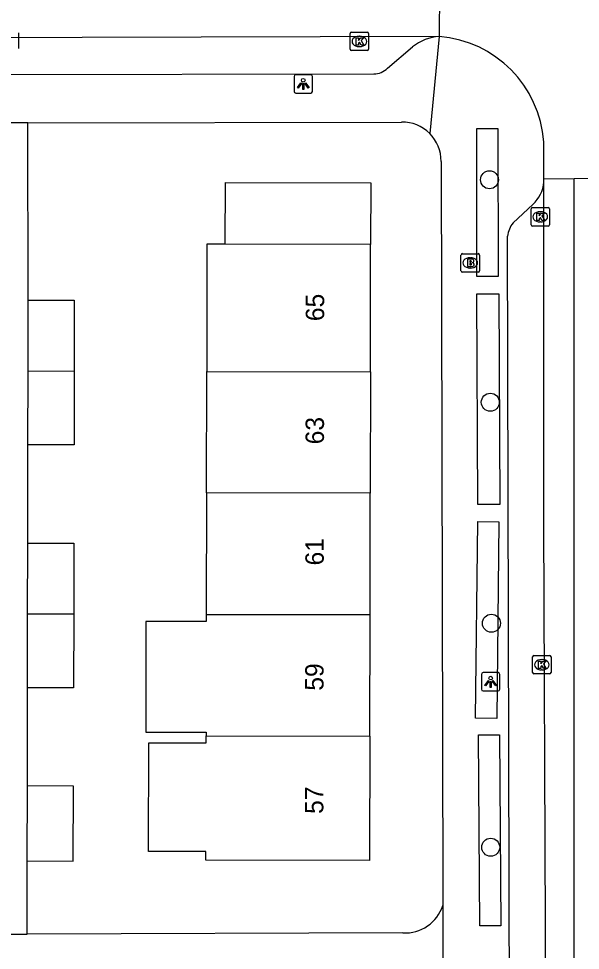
# Model space of a CAD drawing. Extents: x 160732 to 162105, y 387428 to 388479.
# Drawn here: x 161271.9 to 161302.4, y 388097.7 to 388148.3 of the extents above; entities that cross this region are included whole.
import ezdxf

# ---------------------------------------------------------------- set-up
doc = ezdxf.new("R2010")
doc.units = 0
for name, color, linetype in [('IMGEO_Boom', 7, 'Continuous'), ('IMGEO_Brandkraan', 7, 'Continuous'), ('IMGEO_Kolk', 7, 'Continuous'), ('IMGEO_Lichtpunt', 7, 'Continuous'), ('IMGEO_Pand', 7, 'Continuous'), ('IMGEO_Pand_nummerreeks', 7, 'Continuous'), ('IMGEO_Rijbaan_lokaal_gesloten', 7, 'Continuous'), ('IMGEO_Rijbaan_lokaal_open', 7, 'Continuous'), ('IMGEO_Voetpad_open', 7, 'Continuous')]:
    doc.layers.add(name, color=color, linetype=linetype)

msp = doc.modelspace()

# ---------------------------------------------------------------- linework, layer by layer
at = {"layer": 'IMGEO_Boom'}
for centre in [(161297.473, 388139.553), (161297.518, 388127.461), (161297.578, 388115.457), (161297.538, 388103.288)]:
    msp.add_circle(centre, 0.489, dxfattribs=at)
at = {"layer": 'IMGEO_Brandkraan'}
for p, q in [((161295.999, 388135.535), (161296.851, 388135.535)), ((161295.924, 388134.609), (161295.924, 388135.461)), ((161296.412, 388135.315), (161296.437, 388135.315)), ((161296.925, 388135.461), (161296.925, 388134.609)), ((161296.851, 388134.535), (161295.999, 388134.535)), ((161296.435, 388134.755), (161296.41, 388134.755))]:
    msp.add_line(p, q, dxfattribs=at)
for points in [[(161295.999, 388135.535), (161296.851, 388135.535)], [(161295.924, 388134.609), (161295.924, 388135.461)], [(161296.272, 388135.235), (161296.272, 388134.835), (161296.485, 388134.835)], [(161296.503, 388135.235), (161296.272, 388135.235)], [(161296.451, 388135.154), (161296.397, 388135.154), (161296.397, 388135.078)], [(161296.397, 388135.078), (161296.45, 388135.078)], [(161296.459, 388135.002), (161296.397, 388135.002), (161296.397, 388134.921)], [(161296.925, 388135.461), (161296.925, 388134.609)], [(161296.851, 388134.535), (161295.999, 388134.535)], [(161296.397, 388134.921), (161296.459, 388134.921)]]:
    msp.add_lwpolyline(points, dxfattribs=at)
for centre, radius, start, end in [((161296.001, 388135.459), 0.0765, 91.552, 178.448), ((161296.001, 388135.459), 0.0765, 91.552, 178.448), ((161296.849, 388135.459), 0.0765, 1.552, 88.448), ((161296.849, 388135.459), 0.0765, 1.552, 88.448), ((161296.452, 388135.116), 0.0379, 267.8285, 90.9355), ((161296.46, 388134.961), 0.0404, 269.8759, 90.5077), ((161296.507, 388135.09), 0.145, 59.4692, 91.5367), ((161296.532, 388135.137), 0.0922, 285.5137, 58.1501), ((161296.537, 388134.945), 0.105, 301.3115, 78.989), ((161296.001, 388134.611), 0.0765, 181.552, 268.448), ((161296.001, 388134.611), 0.0765, 181.552, 268.448), ((161296.491, 388135.086), 0.251, 268.6676, 293.5347), ((161296.849, 388134.611), 0.0765, 271.552, 358.448), ((161296.849, 388134.611), 0.0765, 271.552, 358.448)]:
    msp.add_arc(centre, radius, start, end, dxfattribs=at)
for centre, major_axis, ratio, start_param, end_param in [((161296.411, 388135.035), (-0.387, 0.002), 0.722429, 4.712389, 7.853982), ((161296.436, 388135.035), (-0.39, 0.002), 0.717154, 1.570796, 4.712389)]:
    msp.add_ellipse(centre, major_axis=major_axis, ratio=ratio, start_param=start_param, end_param=end_param, dxfattribs=at)
at = {"layer": 'IMGEO_Kolk'}
for p, q in [((161271.882, 388147.531), (161271.882, 388146.679)), ((161289.901, 388146.641), (161289.901, 388147.493)), ((161289.976, 388147.567), (161290.828, 388147.567)), ((161290.389, 388147.347), (161290.414, 388147.347)), ((161290.902, 388147.493), (161290.902, 388146.641)), ((161290.412, 388146.787), (161290.387, 388146.787)), ((161290.828, 388146.567), (161289.976, 388146.567)), ((161299.805, 388138.036), (161300.657, 388138.036)), ((161299.73, 388137.11), (161299.73, 388137.962)), ((161300.218, 388137.816), (161300.243, 388137.816)), ((161300.731, 388137.962), (161300.731, 388137.11)), ((161300.657, 388137.036), (161299.805, 388137.036)), ((161300.241, 388137.256), (161300.216, 388137.256)), ((161299.816, 388112.774), (161299.816, 388113.626)), ((161299.891, 388113.7), (161300.743, 388113.7)), ((161300.304, 388113.48), (161300.329, 388113.48)), ((161300.817, 388113.626), (161300.817, 388112.774)), ((161300.327, 388112.92), (161300.302, 388112.92)), ((161300.743, 388112.7), (161299.891, 388112.7))]:
    msp.add_line(p, q, dxfattribs=at)
for points in [[(161271.882, 388147.531), (161271.882, 388146.679)], [(161289.901, 388146.641), (161289.901, 388147.493)], [(161289.976, 388147.567), (161290.828, 388147.567)], [(161290.222, 388147.267), (161290.345, 388147.267), (161290.345, 388147.116), (161290.475, 388147.267), (161290.639, 388147.267), (161290.493, 388147.116), (161290.646, 388146.867), (161290.494, 388146.867), (161290.409, 388147.031), (161290.345, 388146.964), (161290.345, 388146.867), (161290.222, 388146.867), (161290.222, 388147.267)], [(161290.902, 388147.493), (161290.902, 388146.641)], [(161290.828, 388146.567), (161289.976, 388146.567)], [(161299.805, 388138.036), (161300.657, 388138.036)], [(161299.73, 388137.11), (161299.73, 388137.962)], [(161300.051, 388137.736), (161300.174, 388137.736), (161300.174, 388137.585), (161300.304, 388137.736), (161300.468, 388137.736), (161300.322, 388137.585), (161300.475, 388137.336), (161300.323, 388137.336), (161300.238, 388137.5), (161300.174, 388137.433), (161300.174, 388137.336), (161300.051, 388137.336), (161300.051, 388137.736)], [(161300.731, 388137.962), (161300.731, 388137.11)], [(161300.657, 388137.036), (161299.805, 388137.036)], [(161299.816, 388112.774), (161299.816, 388113.626)], [(161299.891, 388113.7), (161300.743, 388113.7)], [(161300.137, 388113.4), (161300.26, 388113.4), (161300.26, 388113.249), (161300.39, 388113.4), (161300.554, 388113.4), (161300.408, 388113.249), (161300.561, 388113), (161300.409, 388113), (161300.324, 388113.164), (161300.26, 388113.097), (161300.26, 388113), (161300.137, 388113), (161300.137, 388113.4)], [(161300.817, 388113.626), (161300.817, 388112.774)], [(161300.743, 388112.7), (161299.891, 388112.7)]]:
    msp.add_lwpolyline(points, dxfattribs=at)
for centre, start, end in [((161289.978, 388147.491), 91.552, 178.448), ((161289.978, 388147.491), 91.552, 178.448), ((161290.826, 388147.491), 1.552, 88.448), ((161290.826, 388147.491), 1.552, 88.448), ((161289.978, 388146.643), 181.552, 268.448), ((161289.978, 388146.643), 181.552, 268.448), ((161290.826, 388146.643), 271.552, 358.448), ((161290.826, 388146.643), 271.552, 358.448), ((161299.807, 388137.96), 91.552, 178.448), ((161299.807, 388137.96), 91.552, 178.448), ((161300.655, 388137.96), 1.552, 88.448), ((161300.655, 388137.96), 1.552, 88.448), ((161299.807, 388137.112), 181.552, 268.448), ((161299.807, 388137.112), 181.552, 268.448), ((161300.655, 388137.112), 271.552, 358.448), ((161300.655, 388137.112), 271.552, 358.448), ((161299.893, 388113.624), 91.552, 178.448), ((161299.893, 388113.624), 91.552, 178.448), ((161300.741, 388113.624), 1.552, 88.448), ((161300.741, 388113.624), 1.552, 88.448), ((161299.893, 388112.776), 181.552, 268.448), ((161299.893, 388112.776), 181.552, 268.448), ((161300.741, 388112.776), 271.552, 358.448), ((161300.741, 388112.776), 271.552, 358.448)]:
    msp.add_arc(centre, 0.0765, start, end, dxfattribs=at)
for centre, major_axis, ratio, start_param, end_param in [((161290.388, 388147.067), (-0.387, 0.002), 0.722429, 4.712389, 7.853982), ((161290.413, 388147.067), (-0.39, 0.002), 0.717154, 1.570796, 4.712389), ((161300.217, 388137.536), (-0.387, 0.002), 0.722429, 4.712389, 7.853982), ((161300.242, 388137.536), (-0.39, 0.002), 0.717154, 1.570796, 4.712389), ((161300.303, 388113.2), (-0.387, 0.002), 0.722429, 4.712389, 7.853982), ((161300.328, 388113.2), (-0.39, 0.002), 0.717154, 1.570796, 4.712389)]:
    msp.add_ellipse(centre, major_axis=major_axis, ratio=ratio, start_param=start_param, end_param=end_param, dxfattribs=at)
at = {"layer": 'IMGEO_Lichtpunt'}
for p, q in [((161286.854, 388145.159), (161286.854, 388144.352)), ((161286.854, 388145.159), (161286.854, 388144.352)), ((161287.756, 388145.254), (161286.948, 388145.254)), ((161287.756, 388145.254), (161286.948, 388145.254)), ((161287.85, 388144.352), (161287.85, 388145.159)), ((161287.85, 388144.352), (161287.85, 388145.159)), ((161286.948, 388144.258), (161287.756, 388144.258)), ((161286.948, 388144.258), (161287.756, 388144.258)), ((161297.94, 388112.774), (161297.132, 388112.774)), ((161297.94, 388112.774), (161297.132, 388112.774)), ((161297.038, 388112.679), (161297.038, 388111.872)), ((161297.038, 388112.679), (161297.038, 388111.872)), ((161298.034, 388111.872), (161298.034, 388112.679)), ((161298.034, 388111.872), (161298.034, 388112.679)), ((161297.132, 388111.778), (161297.94, 388111.778)), ((161297.132, 388111.778), (161297.94, 388111.778))]:
    msp.add_line(p, q, dxfattribs=at)
for points in [[(161287.228, 388144.823), (161287.267, 388144.795), (161287.079, 388144.533), (161287.041, 388144.56), (161287.228, 388144.823)], [(161287.33, 388144.775), (161287.377, 388144.775), (161287.377, 388144.453), (161287.33, 388144.453), (161287.33, 388144.775)], [(161287.44, 388144.795), (161287.478, 388144.822), (161287.665, 388144.56), (161287.626, 388144.532), (161287.44, 388144.795)], [(161297.412, 388112.343), (161297.451, 388112.315), (161297.263, 388112.053), (161297.225, 388112.08), (161297.412, 388112.343)], [(161297.514, 388112.295), (161297.561, 388112.295), (161297.561, 388111.973), (161297.514, 388111.973), (161297.514, 388112.295)], [(161297.624, 388112.315), (161297.662, 388112.342), (161297.849, 388112.08), (161297.81, 388112.052), (161297.624, 388112.315)]]:
    msp.add_lwpolyline(points, dxfattribs=at)
for centre in [(161287.353, 388144.957), (161297.537, 388112.477)]:
    msp.add_circle(centre, 0.0994, dxfattribs=at)
for centre, start, end in [((161286.948, 388145.159), 90, 180), ((161286.948, 388145.159), 90, 180), ((161287.756, 388145.159), 0, 90), ((161287.756, 388145.159), 0, 90), ((161286.948, 388144.352), 180, 270), ((161286.948, 388144.352), 180, 270), ((161287.756, 388144.352), 270, 0), ((161287.756, 388144.352), 270, 360), ((161297.132, 388112.679), 90, 180), ((161297.132, 388112.679), 90, 180), ((161297.94, 388112.679), 0, 90), ((161297.94, 388112.679), 0, 90), ((161297.132, 388111.872), 180, 270), ((161297.132, 388111.872), 180, 270), ((161297.94, 388111.872), 270, 0), ((161297.94, 388111.872), 270, 360)]:
    msp.add_arc(centre, 0.0946, start, end, dxfattribs=at)
at = {"layer": 'IMGEO_Pand'}
for points in [[(161283.115, 388136.046), (161283.121, 388139.396), (161291.019, 388139.383), (161291.013, 388136.036)], [(161283.115, 388136.046), (161282.115, 388136.048), (161282.104, 388129.133)], [(161291.013, 388136.036), (161283.115, 388136.046)], [(161291.002, 388129.123), (161291.013, 388136.036)], [(161272.392, 388129.144), (161272.399, 388133.004)], [(161272.399, 388133.004), (161274.908, 388133), (161274.901, 388129.141)], [(161272.384, 388125.153), (161272.392, 388129.144)], [(161274.901, 388129.141), (161274.893, 388125.148), (161272.384, 388125.153)], [(161274.901, 388129.141), (161272.392, 388129.144)], [(161282.093, 388122.533), (161282.104, 388129.133)], [(161282.104, 388129.133), (161291.002, 388129.123)], [(161291.002, 388129.123), (161290.991, 388122.523)], [(161282.093, 388122.533), (161282.082, 388115.933)], [(161290.991, 388122.523), (161282.093, 388122.533)], [(161290.98, 388115.923), (161290.991, 388122.523)], [(161272.37, 388115.944), (161272.377, 388119.804)], [(161272.377, 388119.804), (161274.886, 388119.8), (161274.879, 388115.941)], [(161272.362, 388111.953), (161272.37, 388115.944)], [(161274.879, 388115.941), (161274.871, 388111.948), (161272.362, 388111.953)], [(161274.879, 388115.941), (161272.37, 388115.944)], [(161282.082, 388115.933), (161282.081, 388115.551), (161278.799, 388115.554), (161278.792, 388109.538), (161282.071, 388109.534), (161282.071, 388109.334)], [(161282.082, 388115.933), (161290.98, 388115.923)], [(161290.969, 388109.324), (161290.98, 388115.923)], [(161290.969, 388109.324), (161290.958, 388102.573), (161282.06, 388102.587), (161282.061, 388103.051), (161278.946, 388103.056), (161278.956, 388108.956), (161282.07, 388108.951), (161282.071, 388109.334)], [(161282.071, 388109.334), (161290.969, 388109.324)], [(161272.34, 388102.539), (161274.844, 388102.524), (161274.869, 388106.602), (161272.366, 388106.617)], [(161272.34, 388102.539), (161272.366, 388106.617)]]:
    msp.add_lwpolyline(points, dxfattribs=at)
at = {"layer": 'IMGEO_Rijbaan_lokaal_gesloten'}
for points in [[(161300.431, 388139.603), (161302.072, 388139.624)], [(161300.432, 388139.424), (161300.431, 388139.603)], [(161302.072, 388139.624), (161305.432, 388139.667)], [(161302.072, 388087.918), (161302.072, 388139.624)], [(161300.616, 388077.151), (161300.427, 388120.911), (161300.432, 388139.424)]]:
    msp.add_lwpolyline(points, dxfattribs=at)
at = {"layer": 'IMGEO_Rijbaan_lokaal_open'}
for points in [[(161294.781, 388152.269), (161294.744, 388147.33)], [(161294.744, 388147.33), (161249.429, 388147.206)], [(161300.431, 388139.603), (161300.417, 388141.607)]]:
    msp.add_lwpolyline(points, dxfattribs=at)
msp.add_arc((161294.263, 388141.18), 6.169, 3.9675, 85.5297, dxfattribs=at)
at = {"layer": 'IMGEO_Voetpad_open'}
for points in [[(161249.429, 388147.206), (161249.466, 388145.236), (161291.181, 388145.302)], [(161294.744, 388147.33), (161294.222, 388142.072)], [(161291.938, 388145.608), (161293.287, 388146.772)], [(161272.383, 388142.648), (161271.067, 388142.646)], [(161272.383, 388142.648), (161292.695, 388142.682)], [(161272.399, 388133.004), (161272.383, 388142.648)], [(161296.789, 388134.289), (161296.779, 388142.327), (161297.931, 388142.329), (161297.941, 388134.291), (161296.789, 388134.289)], [(161294.843, 388140.55), (161294.94, 388100.934), (161294.942, 388100.12)], [(161298.753, 388137.202), (161299.826, 388138.215)], [(161298.593, 388080.37), (161298.448, 388136.488)], [(161296.836, 388121.9), (161296.785, 388133.35), (161297.976, 388133.356), (161298.027, 388121.905), (161296.836, 388121.9)], [(161272.377, 388119.804), (161272.384, 388125.153)], [(161296.714, 388110.296), (161296.835, 388120.976), (161297.984, 388120.963), (161297.863, 388110.283), (161296.714, 388110.296)], [(161272.366, 388106.617), (161272.362, 388111.953)], [(161296.945, 388099.008), (161296.878, 388109.386), (161298.019, 388109.393), (161298.086, 388099.015), (161296.945, 388099.008)], [(161272.352, 388098.565), (161272.34, 388102.539)], [(161294.942, 388100.12), (161294.956, 388093.624)], [(161271.05, 388098.561), (161272.352, 388098.565)], [(161292.762, 388098.628), (161272.352, 388098.565)]]:
    msp.add_lwpolyline(points, dxfattribs=at)
for centre, radius, start, end in [((161294.903, 388144.735), 2.6, 93.4955, 128.4161), ((161291.178, 388146.4), 1.098, 270.178, 313.8418), ((161292.739, 388140.577), 2.106, 45.244, 91.2049), ((161292.735, 388140.578), 2.108, 359.2455, 45.147), ((161298.597, 388139.587), 1.842, 311.8461, 354.9101), ((161299.887, 388136.295), 1.452, 141.3641, 172.3744), ((161292.869, 388100.81), 2.184, 267.1792, 341.5966)]:
    msp.add_arc(centre, radius, start, end, dxfattribs=at)

# ---------------------------------------------------------------- texts
at = {"layer": 'IMGEO_Pand_nummerreeks'}
for s, rotation, p in [('65', 89.9024, (161288.487, 388131.868)), ('63', 89.9024, (161288.476, 388125.175)), ('61', 89.9024, (161288.465, 388118.595)), ('59', 89.9028, (161288.454, 388111.79)), ('57', 89.9028, (161288.443, 388105.097))]:
    msp.add_text(s, height=1, rotation=rotation, dxfattribs=at).set_placement(p)

doc.saveas('drawing.dxf')
